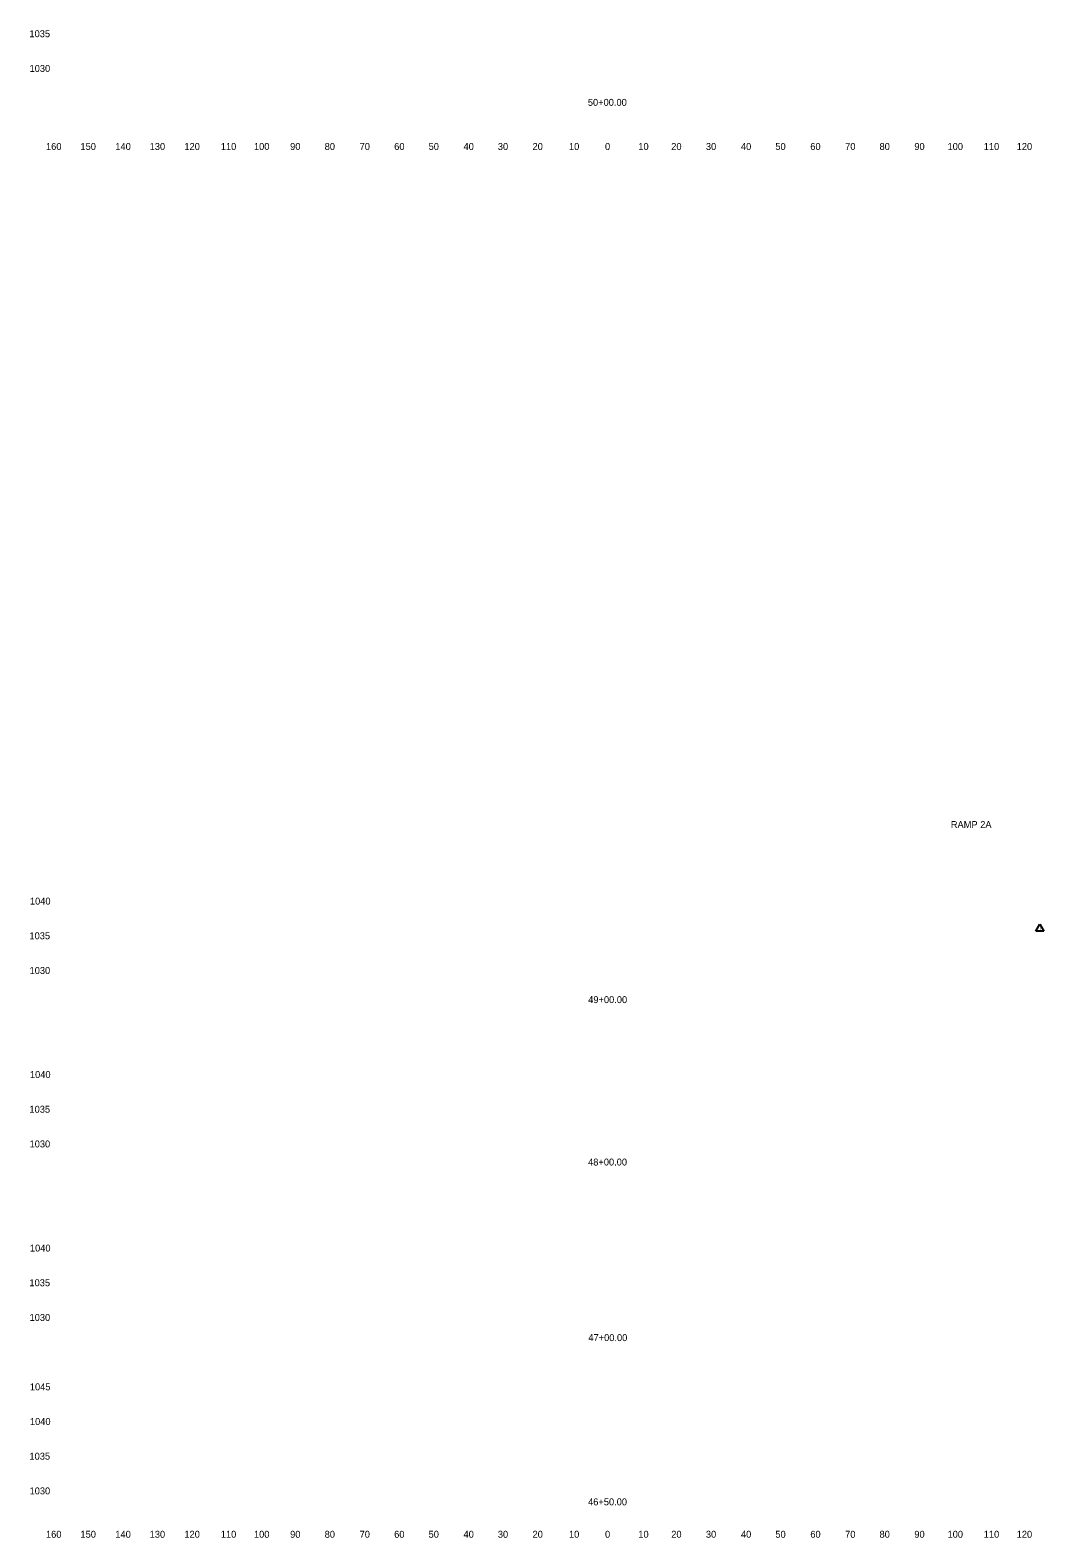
# Model space of a CAD drawing. Extents: x 4994 to 7388, y 4997 to 8804.
# Drawn here: x 4993.5 to 5285.8, y 4997.5 to 5432 of the extents above; entities that cross this region are included whole.
import ezdxf

# ---------------------------------------------------------------- set-up
doc = ezdxf.new("R2010")
doc.units = 0
for name, color, linetype in [('RD_SHT_ID', 7, 'Continuous'), ('RD_SHT_TX', 7, 'Continuous'), ('RD_XS_TX_Offset', 7, 'Continuous'), ('RD_XS_TX_Station', 7, 'Continuous')]:
    doc.layers.add(name, color=color, linetype=linetype)

msp = doc.modelspace()

# ---------------------------------------------------------------- linework, layer by layer
at = {"layer": 'RD_SHT_ID'}
for p, q in [((5283.57, 5172.36), (5284.71, 5174.39)), ((5285.85, 5172.36), (5283.57, 5172.36)), ((5284.71, 5174.39), (5285.85, 5172.36))]:
    msp.add_line(p, q, dxfattribs=at)

# ---------------------------------------------------------------- texts
msp.add_text('RAMP 2A', height=2, dxfattribs=at).set_placement((5259.02, 5202.06))
at = {"layer": 'RD_SHT_TX'}
msp.add_text('1', height=0.88, dxfattribs=at).set_placement((5284.6, 5172.59))
at = {"layer": 'RD_XS_TX_Offset'}
for s, p in [('1035', (4993.33, 5430)), ('1030', (4993.36, 5420)), ('160', (4998.1, 5397.5)), ('150', (5008.04, 5397.5)), ('140', (5018.1, 5397.5)), ('130', (5027.99, 5397.5)), ('120', (5038.01, 5397.5)), ('110', (5048.51, 5397.5)), ('100', (5058.07, 5397.5)), ('90', (5068.5, 5397.5)), ('80', (5078.46, 5397.5)), ('70', (5088.54, 5397.5)), ('60', (5098.5, 5397.5)), ('50', (5108.43, 5397.5)), ('40', (5118.5, 5397.5)), ('30', (5128.39, 5397.5)), ('20', (5138.4, 5397.5)), ('10', (5148.91, 5397.5)), ('0', (5159.3, 5397.5)), ('0', (5159.3, 5397.5)), ('10', (5168.91, 5397.5)), ('20', (5178.4, 5397.5)), ('30', (5188.39, 5397.5)), ('40', (5198.5, 5397.5)), ('50', (5208.43, 5397.5)), ('60', (5218.5, 5397.5)), ('70', (5228.54, 5397.5)), ('80', (5238.46, 5397.5)), ('90', (5248.5, 5397.5)), ('100', (5258.07, 5397.5)), ('110', (5268.51, 5397.5)), ('120', (5278.01, 5397.5)), ('1040', (4993.47, 5180)), ('1035', (4993.33, 5170)), ('1030', (4993.36, 5160)), ('1040', (4993.47, 5130)), ('1035', (4993.33, 5120)), ('1030', (4993.36, 5110)), ('1040', (4993.47, 5080)), ('1035', (4993.33, 5070)), ('1030', (4993.36, 5060)), ('1045', (4993.44, 5040)), ('1040', (4993.47, 5030)), ('1035', (4993.33, 5020)), ('1030', (4993.36, 5010)), ('160', (4998.1, 4997.5)), ('150', (5008.04, 4997.5)), ('140', (5018.1, 4997.5)), ('130', (5027.99, 4997.5)), ('120', (5038.01, 4997.5)), ('110', (5048.51, 4997.5)), ('100', (5058.07, 4997.5)), ('90', (5068.5, 4997.5)), ('80', (5078.46, 4997.5)), ('70', (5088.54, 4997.5)), ('60', (5098.5, 4997.5)), ('50', (5108.43, 4997.5)), ('40', (5118.5, 4997.5)), ('30', (5128.39, 4997.5)), ('20', (5138.4, 4997.5)), ('10', (5148.91, 4997.5)), ('0', (5159.3, 4997.5)), ('0', (5159.3, 4997.5)), ('10', (5168.91, 4997.5)), ('20', (5178.4, 4997.5)), ('30', (5188.39, 4997.5)), ('40', (5198.5, 4997.5)), ('50', (5208.43, 4997.5)), ('60', (5218.5, 4997.5)), ('70', (5228.54, 4997.5)), ('80', (5238.46, 4997.5)), ('90', (5248.5, 4997.5)), ('100', (5258.07, 4997.5)), ('110', (5268.51, 4997.5)), ('120', (5278.01, 4997.5))]:
    msp.add_text(s, height=2, dxfattribs=at).set_placement(p)
at = {"layer": 'RD_XS_TX_Station'}
for s, p in [('50+00.00', (5154.35, 5410.22)), ('49+00.00', (5154.45, 5151.6)), ('48+00.00', (5154.42, 5104.79)), ('47+00.00', (5154.5, 5054.18)), ('46+50.00', (5154.42, 5006.84))]:
    msp.add_text(s, height=2, dxfattribs=at).set_placement(p)

doc.saveas('drawing.dxf')
